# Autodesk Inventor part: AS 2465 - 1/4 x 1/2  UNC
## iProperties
Comments: To add or edit properties for Autodesk Inventor files, use iProperties.
Created: 2005-06
Part Number: AS 2465 - 1/4 x 1/2  UNC
Vendor: Autodesk Inc.
Document SubType Name: Modeling
Designer: John Blackburn
Material: Default
Description: Hex Bolt
Standard: AS 2465
Size Designation: 1/4 x 1/2  UNC
Alert: To add or edit properties for Autodesk Inventor files, use iProperties.
Control State: 0
Master: False
Checked Out: False
Shininess: 64.0
Length Units: 11272
Angle Units: 11279
Time Units: 11290
Mass Units: 11286
Length Display Precision: 3
Angle Display Precision: 2
Compacted: True
EGR: 3
Density: 0.0
Volumn: 0.0
Area: 0.0
PropertySet Name: Model Information
Author: John Blackburn
Revision Number: 8
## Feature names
1. Body [Revolution]
2. Head [Extrusion]
3. Chamfer1 [Revolution]
4. Chamfer2
